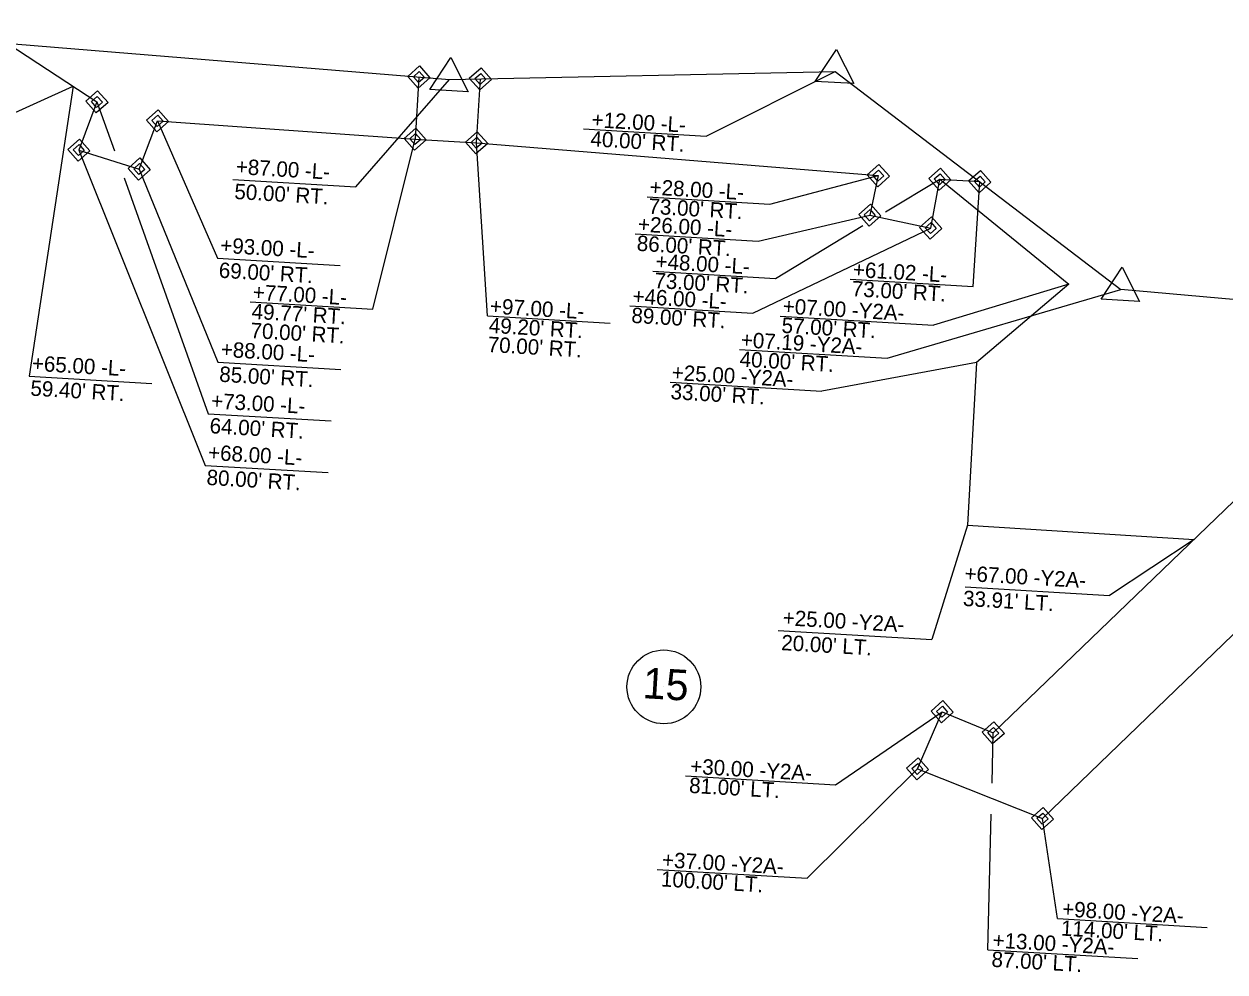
# Model space of a CAD drawing. Extents: x 2010883 to 2014849, y 442000 to 447413.
# Drawn here: x 2012782.2 to 2013172.7, y 444593.2 to 444901.5 of the extents above; entities that cross this region are included whole.
import ezdxf

# ---------------------------------------------------------------- set-up
doc = ezdxf.new("R2010")
doc.units = 0
for name, color, linetype in [('Prop Easement Construction', 7, 'Continuous'), ('Prop Easement Construction Station Offsets', 7, 'Continuous'), ('Prop Easement Permanent Drainage Utility', 7, 'Continuous'), ('Prop Easement Permanent Drainage Utility Station Offsets', 7, 'Continuous'), ('Prop Easement Permanent Utility', 7, 'Continuous'), ('Prop Easement Permanent Utility Station Offsets', 7, 'Continuous'), ('Prop Parcel Number CELL', 7, 'Continuous'), ('Prop Parcel Number Text', 7, 'Continuous'), ('Prop ROW Marker CELL', 7, 'Continuous'), ('Prop ROW Permanent Easement CELL', 7, 'Continuous'), ('Prop ROW RW Lines', 7, 'Continuous'), ('Prop ROW Station Offsets', 7, 'Continuous')]:
    doc.layers.add(name, color=color, linetype=linetype)

msp = doc.modelspace()

# ---------------------------------------------------------------- linework, layer by layer
at = {"layer": 'Prop Easement Construction'}
for p, q in [((2012773.5, 444870.08), (2012798.2, 444881.24)), ((2013079.91, 444851.01), (2013121.94, 444816.92)), ((2013121.94, 444816.92), (2013091.82, 444791.42)), ((2013091.82, 444791.42), (2013088.96, 444738.5)), ((2013088.96, 444738.5), (2013162.67, 444733.89))]:
    msp.add_line(p, q, dxfattribs=at)
at = {"layer": 'Prop Easement Construction Station Offsets'}
for p, q in [((2012798.2, 444881.24), (2012783.82, 444786.97)), ((2013121.94, 444816.92), (2013077.91, 444803.53)), ((2013027.99, 444806.47), (2013077.91, 444803.53)), ((2013091.82, 444791.42), (2013041.55, 444782.09)), ((2012783.82, 444786.97), (2012823.75, 444784.62)), ((2012992.28, 444784.99), (2013041.55, 444782.09)), ((2013088.96, 444738.5), (2013077.33, 444701.31)), ((2013162.67, 444733.89), (2013135.11, 444715.67)), ((2013088.19, 444718.44), (2013135.11, 444715.67)), ((2013027.41, 444704.26), (2013077.33, 444701.31))]:
    msp.add_line(p, q, dxfattribs=at)
at = {"layer": 'Prop Easement Permanent Drainage Utility'}
for p, q in [((2012910.58, 444884.26), (2012909.39, 444864.07)), ((2012929.35, 444862.89), (2012930.58, 444883.66)), ((2012909.39, 444864.07), (2012929.35, 444862.89))]:
    msp.add_line(p, q, dxfattribs=at)
at = {"layer": 'Prop Easement Permanent Drainage Utility Station Offsets'}
for p, q in [((2012895.66, 444808.76), (2012909.39, 444864.07)), ((2012932.84, 444806.56), (2012929.35, 444862.89)), ((2012855.73, 444811.11), (2012895.66, 444808.76)), ((2012932.84, 444806.56), (2012972.77, 444804.21))]:
    msp.add_line(p, q, dxfattribs=at)
at = {"layer": 'Prop Easement Permanent Utility'}
for p, q in [((2012776.99, 444895.16), (2012805.92, 444876.18)), ((2012805.92, 444876.18), (2012799.99, 444860.5)), ((2012819.66, 444854.33), (2012825.59, 444870.01)), ((2012825.59, 444870.01), (2012909.39, 444864.07)), ((2012929.35, 444862.89), (2013059.95, 444852.19)), ((2012799.99, 444860.5), (2012819.66, 444854.33)), ((2013059.95, 444852.19), (2013057.19, 444839.33)), ((2013076.98, 444835.16), (2013079.91, 444851.01)), ((2013079.91, 444851.01), (2013092.91, 444850.25)), ((2013057.19, 444839.33), (2013076.98, 444835.16)), ((2013097.33, 444670.95), (2013257.77, 444825.74)), ((2013113.33, 444643.09), (2013295.16, 444818.72)), ((2013072.67, 444659.27), (2013080.68, 444677.86)), ((2013080.68, 444677.86), (2013097.33, 444670.95)), ((2013072.67, 444659.27), (2013113.33, 444643.09)), ((2013073.19, 444659.21), (2013073.19, 444659.21))]:
    msp.add_line(p, q, dxfattribs=at)
at = {"layer": 'Prop Easement Permanent Utility Station Offsets'}
for p, q in [((2012805.92, 444876.18), (2012811.58, 444860.31)), ((2012825.59, 444870.01), (2012845.07, 444825.34)), ((2012799.99, 444860.5), (2012841.09, 444757.96)), ((2012819.66, 444854.33), (2012845.23, 444791.51)), ((2012814.71, 444851.52), (2012842.08, 444774.76)), ((2013024.69, 444842.93), (2013059.95, 444852.19)), ((2013062.29, 444840.38), (2013079.91, 444851.01)), ((2013090.78, 444816.12), (2013092.91, 444850.25)), ((2012984.76, 444845.29), (2013024.69, 444842.93)), ((2013020.88, 444830.89), (2013057.19, 444839.33)), ((2013019.13, 444807.44), (2013076.98, 444835.16)), ((2013026.49, 444818.78), (2013054.95, 444835.95)), ((2012980.95, 444833.24), (2013020.88, 444830.89)), ((2012845.07, 444825.34), (2012885, 444822.98)), ((2012986.68, 444821.13), (2013026.49, 444818.78)), ((2013050.85, 444818.48), (2013090.78, 444816.12)), ((2012979.2, 444809.8), (2013019.13, 444807.44)), ((2012845.23, 444791.51), (2012885.16, 444789.16)), ((2012842.08, 444774.76), (2012882.02, 444772.4)), ((2012841.09, 444757.96), (2012881.03, 444755.61)), ((2013045.98, 444654.11), (2013080.68, 444677.86)), ((2013096.93, 444654.63), (2013097.33, 444670.95)), ((2013036.82, 444623.68), (2013072.67, 444659.27)), ((2012997.27, 444656.98), (2013045.98, 444654.11)), ((2013095.58, 444600.42), (2013096.67, 444644.51)), ((2013118.18, 444610.56), (2013113.33, 444643.09)), ((2012988.1, 444626.55), (2013036.82, 444623.68)), ((2013118.18, 444610.56), (2013166.89, 444607.69)), ((2013095.58, 444600.42), (2013144.29, 444597.54))]:
    msp.add_line(p, q, dxfattribs=at)
at = {"layer": 'Prop Parcel Number CELL'}
msp.add_line((2012990.22, 444685.93), (2012990.22, 444685.93), dxfattribs=at)
msp.add_circle((2012990.22, 444685.93), 12, dxfattribs=at)
at = {"layer": 'Prop ROW Marker CELL'}
for p, q in [((2013045.92, 444886.07), (2013045.92, 444886.07)), ((2012910.58, 444884.26), (2012910.58, 444884.26)), ((2012920.55, 444883.45), (2012920.55, 444883.45)), ((2012930.58, 444883.66), (2012930.58, 444883.66)), ((2012805.92, 444876.18), (2012805.92, 444876.18)), ((2012825.59, 444870.01), (2012825.59, 444870.01)), ((2012909.39, 444864.07), (2012909.39, 444864.07)), ((2012929.35, 444862.89), (2012929.35, 444862.89)), ((2012799.99, 444860.5), (2012799.99, 444860.5)), ((2012819.66, 444854.33), (2012819.66, 444854.33)), ((2013059.95, 444852.19), (2013059.95, 444852.19)), ((2013079.91, 444851.01), (2013079.91, 444851.01)), ((2013092.91, 444850.25), (2013092.91, 444850.25)), ((2013057.19, 444839.33), (2013057.19, 444839.33)), ((2013076.98, 444835.16), (2013076.98, 444835.16)), ((2013138.85, 444815.21), (2013138.85, 444815.21)), ((2013080.68, 444677.86), (2013080.68, 444677.86)), ((2013097.33, 444670.95), (2013097.33, 444670.95)), ((2013072.67, 444659.27), (2013072.67, 444659.27)), ((2013113.33, 444643.09), (2013113.33, 444643.09))]:
    msp.add_line(p, q, dxfattribs=at)
for points in [[(2013039.47, 444882.85), (2013046.34, 444893.26), (2013051.94, 444882.11)], [(2012914.09, 444880.22), (2012920.97, 444890.63), (2012926.57, 444879.48)], [(2013132.4, 444811.99), (2013139.28, 444822.4), (2013144.88, 444811.25)]]:
    msp.add_lwpolyline(points, close=True, dxfattribs=at)
at = {"layer": 'Prop ROW Permanent Easement CELL'}
for points in [[(2012910.79, 444887.85), (2012914.17, 444884.05), (2012910.36, 444880.67), (2012906.98, 444884.47)], [(2012910.68, 444886.06), (2012912.37, 444884.15), (2012910.47, 444882.46), (2012908.78, 444884.37)], [(2012930.79, 444887.25), (2012934.17, 444883.44), (2012930.36, 444880.06), (2012926.98, 444883.87)], [(2012930.68, 444885.45), (2012932.37, 444883.55), (2012930.47, 444881.86), (2012928.78, 444883.76)], [(2012806.13, 444879.77), (2012809.51, 444875.97), (2012805.71, 444872.59), (2012802.33, 444876.39)], [(2012806.03, 444877.98), (2012807.72, 444876.07), (2012805.81, 444874.38), (2012804.12, 444876.28)], [(2012825.8, 444873.6), (2012829.18, 444869.8), (2012825.38, 444866.42), (2012822, 444870.22)], [(2012825.7, 444871.81), (2012827.39, 444869.9), (2012825.48, 444868.21), (2012823.79, 444870.12)], [(2012909.6, 444867.66), (2012912.98, 444863.86), (2012909.17, 444860.48), (2012905.79, 444864.28)], [(2012909.49, 444865.87), (2012911.18, 444863.96), (2012909.28, 444862.27), (2012907.59, 444864.18)], [(2012929.56, 444866.49), (2012932.95, 444862.68), (2012929.14, 444859.3), (2012925.76, 444863.1)], [(2012800.2, 444864.09), (2012803.58, 444860.29), (2012799.77, 444856.91), (2012796.39, 444860.71)], [(2012800.09, 444862.3), (2012801.78, 444860.4), (2012799.88, 444858.7), (2012798.19, 444860.61)], [(2012929.46, 444864.69), (2012931.15, 444862.79), (2012929.25, 444861.1), (2012927.55, 444863)], [(2012819.87, 444857.93), (2012823.25, 444854.12), (2012819.45, 444850.74), (2012816.06, 444854.54)], [(2012819.76, 444856.13), (2012821.45, 444854.23), (2012819.55, 444852.54), (2012817.86, 444854.44)], [(2013060.16, 444855.78), (2013063.54, 444851.98), (2013059.74, 444848.6), (2013056.35, 444852.4)], [(2013060.05, 444853.99), (2013061.74, 444852.08), (2013059.84, 444850.39), (2013058.15, 444852.29)], [(2013080.13, 444854.61), (2013083.51, 444850.8), (2013079.7, 444847.42), (2013076.32, 444851.22)], [(2013093.12, 444853.84), (2013096.5, 444850.03), (2013092.69, 444846.65), (2013089.31, 444850.46)], [(2013080.02, 444852.81), (2013081.71, 444850.91), (2013079.81, 444849.22), (2013078.12, 444851.12)], [(2013093.01, 444852.04), (2013094.7, 444850.14), (2013092.8, 444848.45), (2013091.11, 444850.35)], [(2013057.4, 444842.92), (2013060.78, 444839.12), (2013056.97, 444835.74), (2013053.59, 444839.54)], [(2013057.29, 444841.13), (2013058.98, 444839.22), (2013057.08, 444837.53), (2013055.39, 444839.44)], [(2013077.19, 444838.75), (2013080.57, 444834.95), (2013076.76, 444831.56), (2013073.38, 444835.37)], [(2013077.08, 444836.95), (2013078.77, 444835.05), (2013076.87, 444833.36), (2013075.18, 444835.26)], [(2013080.89, 444681.45), (2013084.27, 444677.65), (2013080.47, 444674.27), (2013077.09, 444678.07)], [(2013080.79, 444679.66), (2013082.48, 444677.75), (2013080.57, 444676.06), (2013078.88, 444677.97)], [(2013097.54, 444674.55), (2013100.93, 444670.74), (2013097.12, 444667.36), (2013093.74, 444671.16)], [(2013097.44, 444672.75), (2013099.13, 444670.85), (2013097.23, 444669.16), (2013095.54, 444671.06)], [(2013072.88, 444662.86), (2013076.26, 444659.05), (2013072.45, 444655.67), (2013069.07, 444659.48)], [(2013072.77, 444661.06), (2013074.46, 444659.16), (2013072.56, 444657.47), (2013070.87, 444659.37)], [(2013113.54, 444646.68), (2013116.92, 444642.88), (2013113.11, 444639.5), (2013109.73, 444643.3)], [(2013113.43, 444644.89), (2013115.12, 444642.98), (2013113.22, 444641.29), (2013111.53, 444643.2)]]:
    msp.add_lwpolyline(points, close=True, dxfattribs=at)
at = {"layer": 'Prop ROW RW Lines'}
for p, q in [((2012699.22, 444901.5), (2012920.55, 444883.45)), ((2012920.55, 444883.45), (2013045.92, 444886.07)), ((2013045.92, 444886.07), (2013138.85, 444815.21)), ((2013214.55, 444808.42), (2013138.85, 444815.21))]:
    msp.add_line(p, q, dxfattribs=at)
at = {"layer": 'Prop ROW Station Offsets'}
for p, q in [((2013004, 444865.07), (2013045.92, 444886.07)), ((2012890.05, 444848.58), (2012920.55, 444883.45)), ((2012964.07, 444867.42), (2013004, 444865.07)), ((2012850.12, 444850.93), (2012890.05, 444848.58)), ((2013062.78, 444792.8), (2013138.85, 444815.21)), ((2013014.86, 444795.63), (2013062.78, 444792.8))]:
    msp.add_line(p, q, dxfattribs=at)

# ---------------------------------------------------------------- texts
at = {"layer": 'Prop Easement Construction Station Offsets'}
for s, p in [('+07.00 -Y2A-', (2013028.77, 444807.33)), ("57.00' RT.", (2013028.4, 444801.09)), ('+65.00 -L-', (2012784.65, 444788.76)), ('+25.00 -Y2A-', (2012992.68, 444785.76)), ("59.40' RT.", (2012784.17, 444780.65)), ("33.00' RT.", (2012992.31, 444779.53)), ('+67.00 -Y2A-', (2013087.86, 444720.39)), ("33.91' LT.", (2013087.38, 444712.28)), ('+25.00 -Y2A-', (2013028.77, 444706.01)), ("20.00' LT.", (2013028.29, 444697.9))]:
    msp.add_text(s, height=5, rotation=356.6264, dxfattribs=at).set_placement(p)
at = {"layer": 'Prop Easement Permanent Drainage Utility Station Offsets'}
for s, p in [('+77.00 -L-', (2012856.46, 444811.88)), ('+97.00 -L-', (2012933.57, 444807.34)), ("49.77' RT.", (2012856.1, 444805.64)), ("70.00' RT.", (2012855.73, 444799.4)), ("49.20' RT.", (2012933.21, 444801.1)), ("70.00' RT.", (2012932.84, 444794.86))]:
    msp.add_text(s, height=5, rotation=356.6264, dxfattribs=at).set_placement(p)
at = {"layer": 'Prop Easement Permanent Utility Station Offsets'}
for s, p in [('+28.00 -L-', (2012985.49, 444846.06)), ("73.00' RT.", (2012985.12, 444839.82)), ('+26.00 -L-', (2012981.69, 444834.01)), ('+93.00 -L-', (2012845.9, 444827.12)), ("86.00' RT.", (2012981.32, 444827.77)), ('+48.00 -L-', (2012987.41, 444821.9)), ("69.00' RT.", (2012845.42, 444819.01)), ('+61.02 -L-', (2013051.58, 444819.25)), ("73.00' RT.", (2012987.04, 444815.66)), ('+46.00 -L-', (2012979.93, 444810.57)), ("73.00' RT.", (2013051.22, 444813.01)), ("89.00' RT.", (2012979.56, 444804.33)), ('+88.00 -L-', (2012846.06, 444793.3)), ("85.00' RT.", (2012845.58, 444785.19)), ('+73.00 -L-', (2012842.92, 444776.54)), ("64.00' RT.", (2012842.44, 444768.43)), ('+68.00 -L-', (2012841.93, 444759.75)), ("80.00' RT.", (2012841.45, 444751.64)), ('+30.00 -Y2A-', (2012998.7, 444657.71)), ("81.00' LT.", (2012998.33, 444651.48)), ('+37.00 -Y2A-', (2012989.53, 444627.28)), ("100.00' LT.", (2012989.17, 444621.05)), ('+98.00 -Y2A-', (2013119.61, 444611.3)), ("114.00' LT.", (2013119.24, 444605.06)), ('+13.00 -Y2A-', (2013097, 444601.15)), ("87.00' LT.", (2013096.64, 444594.91))]:
    msp.add_text(s, height=5, rotation=356.6264, dxfattribs=at).set_placement(p)
at = {"layer": 'Prop Parcel Number Text'}
msp.add_text('15', height=10, rotation=356.6264, dxfattribs=at).set_placement((2012983.16, 444682.28))
at = {"layer": 'Prop ROW Station Offsets'}
for s, p in [('+12.00 -L-', (2012966.62, 444867.99)), ("40.00' RT.", (2012966.25, 444861.75)), ('+87.00 -L-', (2012850.95, 444852.72)), ("50.00' RT.", (2012850.48, 444844.61)), ('+07.19 -Y2A-', (2013015.13, 444796.37)), ("40.00' RT.", (2013014.76, 444790.13))]:
    msp.add_text(s, height=5, rotation=356.6264, dxfattribs=at).set_placement(p)

doc.saveas('drawing.dxf')
